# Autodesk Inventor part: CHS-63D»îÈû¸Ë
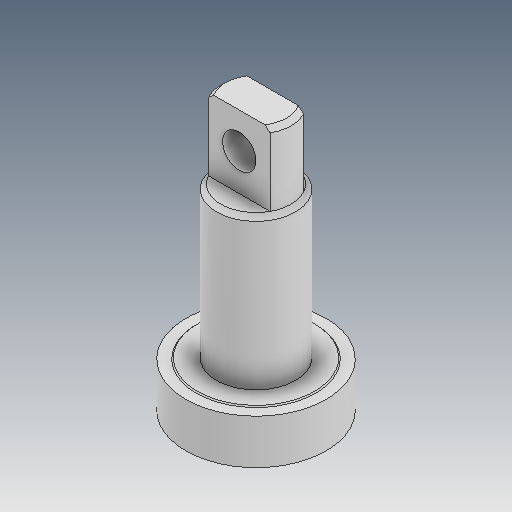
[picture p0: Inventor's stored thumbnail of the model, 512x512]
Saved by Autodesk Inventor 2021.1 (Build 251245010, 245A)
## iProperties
Created: 2021-05
Part Number: CHS-63D»îÈû¸Ë
Material: Ogólny
Document SubType Name: Modeling
Designer: user
Density: 1 g/cm^3
Appearance: Domyślna
Author: user
Revision Number: ÈÎºÎ
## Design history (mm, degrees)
feature "µ¹½Ç1"
node "Bryła1"
